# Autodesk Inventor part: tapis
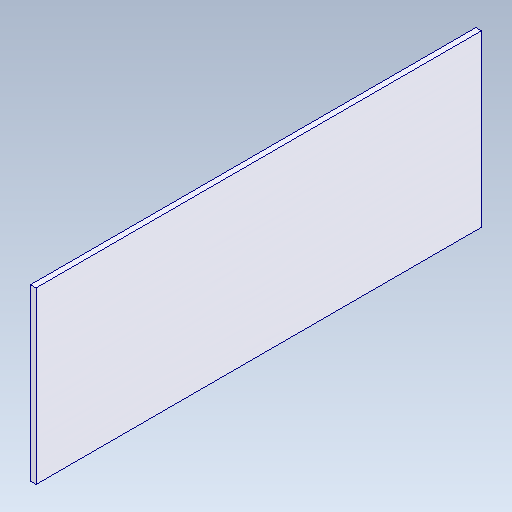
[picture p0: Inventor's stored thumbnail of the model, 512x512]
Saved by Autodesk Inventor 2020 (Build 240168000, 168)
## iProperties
Created: 2021-10
Part Number: tapis
Material: Générique
Document SubType Name: Modeling
Designer: bruno
Density: 1 g/cm^3
Appearance: Blanc froid
Mass: 2445.06 g
Surface Area: 5111.25 cm^2
Volume: 2445.06 cm^3
Author: bruno
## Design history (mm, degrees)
sketch "Esquisse1"
  geometry: L1 (0, 0)-(305.633, 0); L2 (305.633, 0)-(305.633, -800); L3 (305.633, -800)-(0, -800); L4 (0, -800)-(0, 0)
  constraints: 8 end point, 2 parallel, 1 horizontal, 1 perpendicular
  dimensions: "d2" = 800 distance of L1.end L2.end
extrude "Extrusion1" new body sketch "Esquisse1" distance "d0" = 10; taper "d1" = 0 deg
node "Solide1"
